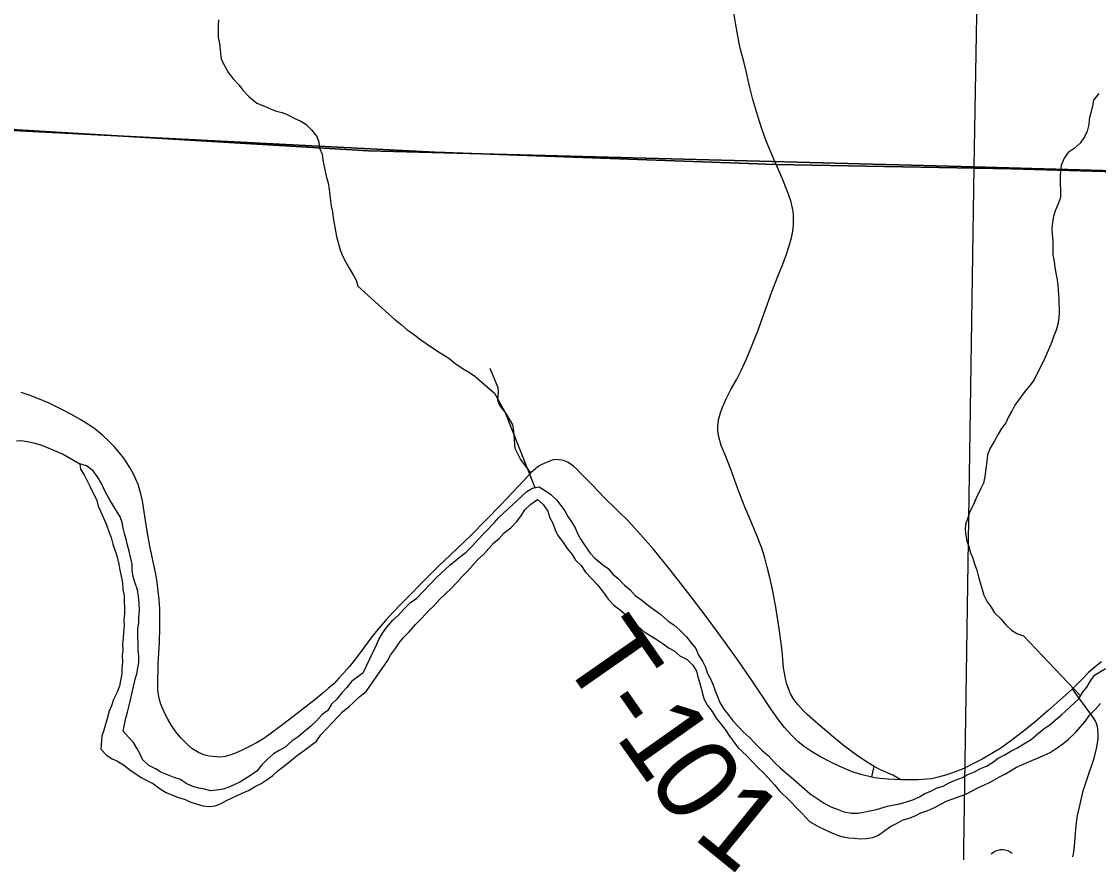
# Model space of a CAD drawing. Extents: x -3.3 to 34, y 0 to 56.8.
# Drawn here: x 2.13 to 2.868, y 32.927 to 33.496 of the extents above; entities that cross this region are included whole.
import ezdxf

# ---------------------------------------------------------------- set-up
doc = ezdxf.new("R2010")
doc.units = 0
for name, color, linetype in [('GM_X_Corporation', 7, 'Continuous'), ('GM_X_Major_River', 7, 'Continuous'), ('GM_X_Township_Road', 7, 'Continuous'), ('GM_X_Township_Road_Text', 7, 'Continuous'), ('GT_Project_Soil_Layers', 7, 'Continuous')]:
    doc.layers.add(name, color=color, linetype=linetype)

msp = doc.modelspace()

# ---------------------------------------------------------------- linework, layer by layer
at = {"layer": 'GM_X_Corporation'}
for points in [[(3.49607, 33.37476), (3.49607, 34.87705), (1.84017, 34.87705), (1.83943, 34.85654), (1.8337, 34.72257), (1.81648, 34.17132), (1.79797, 33.59224), (1.79014, 33.43939), (2.04414, 33.4254), (2.41358, 33.40641), (2.64712, 33.39799), (2.80866, 33.39507), (3.4269, 33.3772)], [(1.82548, 34.44632), (2.80077, 34.41851), (2.78283, 33.39643), (2.36801, 33.40744), (1.79067, 33.44183), (1.79698, 33.59314)], [(3.49607, 33.37604), (3.49607, 34.39505), (2.80077, 34.41851), (2.78283, 33.39643)], [(1.79067, 33.44183), (2.36801, 33.40744), (2.78283, 33.39643), (2.76783, 32.40095), (1.75455, 32.44832), (1.75705, 32.57759)], [(3.49607, 32.37106), (3.49607, 33.37604), (2.78283, 33.39643), (2.76783, 32.40095)]]:
    msp.add_lwpolyline(points, close=True, dxfattribs=at)
msp.add_lwpolyline([(3.4269, 33.3772), (2.80866, 33.39507), (2.64712, 33.39799), (2.41358, 33.40641), (2.04414, 33.4254), (1.79014, 33.43939), (1.78315, 33.26936), (1.7602, 32.71145), (1.75838, 32.6672), (1.75808, 32.65987), (1.75537, 32.59405), (1.74928, 32.44591), (1.74848, 32.4264), (1.74609, 32.36849), (1.74587, 32.36303), (1.69805, 31.56614)], dxfattribs=at)
at = {"layer": 'GM_X_Major_River'}
for points in [[(2.36432, 33.04977), (2.37352, 33.0689), (2.37499, 33.07272), (2.37759, 33.07693), (2.38057, 33.08116), (2.38469, 33.08577), (2.38844, 33.08924), (2.39218, 33.09347), (2.39705, 33.0981), (2.40081, 33.10081), (2.41467, 33.11506), (2.42367, 33.12354), (2.43118, 33.12972), (2.43494, 33.13243), (2.43869, 33.13628), (2.44243, 33.14051), (2.45404, 33.15245), (2.4574, 33.15629), (2.47653, 33.17403), (2.4803, 33.17636), (2.48484, 33.17718), (2.48867, 33.17495), (2.49289, 33.17197), (2.49673, 33.16822), (2.49982, 33.16446), (2.50253, 33.16069), (2.50448, 33.15692), (2.50719, 33.15316), (2.50952, 33.14901), (2.51148, 33.14485), (2.51343, 33.14108), (2.51962, 33.13204), (2.52309, 33.12828), (2.52847, 33.1238), (2.5323, 33.12119), (2.53539, 33.11743), (2.53923, 33.11406), (2.54346, 33.10993), (2.5473, 33.10657), (2.55077, 33.10281), (2.55537, 33.09945), (2.55998, 33.09571), (2.56841, 33.08975), (2.57341, 33.08525), (2.57724, 33.08264), (2.58185, 33.07852), (2.5857, 33.07477), (2.58918, 33.07026), (2.59227, 33.0665), (2.59423, 33.06196), (2.59694, 33.05782), (2.5989, 33.05367), (2.60008, 33.04988), (2.60242, 33.04573), (2.60399, 33.04195), (2.60557, 33.03741), (2.60714, 33.03363), (2.60871, 33.02947), (2.61143, 33.02495), (2.61452, 33.02119), (2.618, 33.01667), (2.62493, 33.00916), (2.62916, 33.00542), (2.6334, 33.00092), (2.63763, 32.99679), (2.64224, 32.99267), (2.64609, 32.98854), (2.65033, 32.98442), (2.65493, 32.98068), (2.65916, 32.97693), (2.67069, 32.96683), (2.67605, 32.9631), (2.68027, 32.9605), (2.68486, 32.95789), (2.68905, 32.95643), (2.69363, 32.95459), (2.69897, 32.95352), (2.70352, 32.95358), (2.70731, 32.95439), (2.71147, 32.95521), (2.71602, 32.95603), (2.72358, 32.95841), (2.72813, 32.95923), (2.73191, 32.96004), (2.73607, 32.96124), (2.74099, 32.96282), (2.74552, 32.96479), (2.74929, 32.96712), (2.75344, 32.96869), (2.75721, 32.97064), (2.76175, 32.97222), (2.76552, 32.97417), (2.77005, 32.97614), (2.77496, 32.9781), (2.77873, 32.98005), (2.78326, 32.98201), (2.78703, 32.98396), (2.79156, 32.98592), (2.79571, 32.98826), (2.79946, 32.99135), (2.80361, 32.99331)], [(2.3664, 33.03688), (2.38088, 33.05797), (2.38311, 33.06181), (2.38646, 33.06641), (2.38907, 33.07025), (2.39206, 33.07409), (2.3958, 33.07794), (2.40029, 33.08294), (2.40441, 33.08717), (2.40853, 33.09179), (2.41265, 33.09564), (2.41677, 33.10026), (2.42464, 33.10759), (2.42876, 33.11182), (2.43213, 33.11567), (2.43587, 33.11952), (2.44261, 33.12721), (2.44711, 33.13107), (2.45384, 33.13876), (2.4576, 33.14185), (2.46096, 33.1457), (2.46547, 33.14918), (2.46959, 33.15341), (2.47258, 33.15725), (2.47518, 33.16147), (2.4793, 33.16532), (2.48382, 33.16842), (2.48766, 33.16506), (2.49076, 33.16054), (2.49234, 33.156), (2.49429, 33.15222), (2.49587, 33.14768), (2.49782, 33.14391), (2.50091, 33.13977), (2.50401, 33.13487), (2.50749, 33.13074), (2.50982, 33.12697), (2.51366, 33.12322), (2.51676, 33.1187), (2.52485, 33.11007), (2.5291, 33.1048), (2.5322, 33.10028), (2.53605, 33.09615), (2.54065, 33.09279), (2.54565, 33.0883), (2.54949, 33.08493), (2.55296, 33.08118), (2.5568, 33.07781), (2.56446, 33.07335), (2.56982, 33.06962), (2.57366, 33.06701), (2.57748, 33.06478), (2.58132, 33.06141), (2.5863, 33.05882), (2.59014, 33.05507), (2.59286, 33.05092), (2.59367, 33.04713), (2.59486, 33.04335), (2.59605, 33.03918), (2.59686, 33.03539), (2.59805, 33.03161), (2.60039, 33.02746), (2.60348, 33.02332), (2.6062, 33.0188), (2.60929, 33.01504), (2.61238, 33.0109), (2.61548, 33.00638), (2.61819, 33.00261), (2.62128, 32.99847), (2.62705, 32.99323), (2.6309, 32.9891), (2.63437, 32.98535), (2.63937, 32.98047), (2.6463, 32.97296), (2.64939, 32.9692), (2.65747, 32.96133), (2.66133, 32.9572), (2.66517, 32.95345), (2.67018, 32.94782), (2.67707, 32.94411), (2.68548, 32.94004), (2.6893, 32.93857), (2.69311, 32.93748), (2.69691, 32.93677), (2.70109, 32.93645), (2.7049, 32.93612), (2.70907, 32.93617), (2.71362, 32.937), (2.71739, 32.93857), (2.72191, 32.94167), (2.72567, 32.94438), (2.72944, 32.94633), (2.73434, 32.94905), (2.7385, 32.95025), (2.74266, 32.95182), (2.74643, 32.95378), (2.75134, 32.95536), (2.75549, 32.95732), (2.76454, 32.962), (2.76908, 32.96358), (2.77285, 32.96515)], [(2.80361, 32.99331), (2.80813, 32.99603), (2.81266, 32.99837), (2.81718, 33.00109), (2.82207, 33.00419), (2.82583, 33.00728), (2.83109, 33.01154), (2.83485, 33.01425), (2.8386, 33.01734), (2.84273, 33.02081), (2.85473, 33.032), (2.85734, 33.03621), (2.86032, 33.04005), (2.86255, 33.04388), (2.86553, 33.0481), (2.87306, 33.05276)], [(2.77285, 32.96515), (2.77739, 32.96673), (2.78644, 32.97141), (2.79022, 32.97299), (2.79399, 32.97494), (2.8004, 32.97844), (2.80417, 32.98039), (2.80793, 32.98272), (2.81208, 32.98506), (2.81736, 32.98741), (2.82265, 32.98976), (2.82642, 32.99133), (2.83095, 32.99329), (2.8351, 32.99525), (2.84, 32.99835), (2.84376, 33.00107), (2.84751, 33.00415), (2.85239, 33.00878), (2.85912, 33.01647), (2.8621, 33.02069), (2.86622, 33.02493), (2.86959, 33.02877)]]:
    msp.add_lwpolyline(points, dxfattribs=at)
at = {"layer": 'GM_X_Township_Road'}
for points in [[(2.64306, 33.40812), (2.64, 33.41532), (2.63746, 33.42258), (2.63475, 33.43116), (2.63146, 33.44258), (2.62899, 33.45179), (2.62694, 33.461), (2.62513, 33.46865), (2.62274, 33.47769), (2.62167, 33.48229), (2.61954, 33.49511), (2.61781, 33.50481)], [(2.73274, 32.9765), (2.72726, 32.97959), (2.71883, 32.98333), (2.71446, 32.98551), (2.7085, 32.9892), (2.7021, 32.99366), (2.69449, 32.99921), (2.68672, 33.00568), (2.67581, 33.01483), (2.66855, 33.02125), (2.66564, 33.02408), (2.66222, 33.02796), (2.65944, 33.03148), (2.65722, 33.03536), (2.65593, 33.03841), (2.65454, 33.04267), (2.65357, 33.04697), (2.65302, 33.04958), (2.65249, 33.05325), (2.65139, 33.06477), (2.64964, 33.07864), (2.64706, 33.09469), (2.64482, 33.10697), (2.64284, 33.11599), (2.64128, 33.12212), (2.63962, 33.1285), (2.63747, 33.1352), (2.63506, 33.14165), (2.63216, 33.14883), (2.62605, 33.16289), (2.62125, 33.1751), (2.61662, 33.1886), (2.61283, 33.1979), (2.60969, 33.20558), (2.60806, 33.21151), (2.60744, 33.2153), (2.6073, 33.21885), (2.60792, 33.22314), (2.60921, 33.22787), (2.61052, 33.23172), (2.6132, 33.23761), (2.6164, 33.2439), (2.62036, 33.25108), (2.62327, 33.25701), (2.62698, 33.26489), (2.63077, 33.27377), (2.63466, 33.28339), (2.639, 33.2955), (2.64363, 33.30891), (2.64834, 33.32084), (2.65186, 33.32981), (2.65417, 33.33591), (2.6563, 33.34239), (2.65778, 33.34775), (2.6587, 33.35237), (2.65925, 33.35663), (2.65935, 33.36097), (2.65925, 33.36449), (2.65861, 33.36819), (2.65732, 33.37318), (2.65546, 33.37892), (2.65139, 33.38872), (2.6465, 33.4), (2.64344, 33.40722), (2.64306, 33.40812)], [(2.47911, 33.18675), (2.4722, 33.19606), (2.46838, 33.20337), (2.46764, 33.21549), (2.46693, 33.21961), (2.46242, 33.22749), (2.4577, 33.23329), (2.45654, 33.23661), (2.45709, 33.24222), (2.45684, 33.24508), (2.4514, 33.25821)], [(2.73274, 32.9765), (2.72404, 32.97682), (2.71874, 32.97737), (2.71498, 32.97786), (2.71299, 32.97825), (2.70542, 32.98005), (2.6989, 32.98226), (2.69098, 32.98552), (2.68482, 32.98852), (2.67777, 32.99222), (2.67157, 32.99592), (2.66675, 32.99913), (2.66241, 33.00257), (2.65761, 33.00738), (2.65303, 33.01241), (2.64846, 33.01825), (2.64366, 33.0251), (2.63176, 33.04283), (2.6217, 33.05747), (2.61198, 33.07131), (2.59929, 33.08846), (2.58682, 33.10481), (2.5747, 33.12026), (2.56315, 33.13466), (2.55422, 33.14484), (2.54611, 33.15376), (2.53822, 33.16154), (2.52941, 33.17), (2.52129, 33.17848), (2.51306, 33.1868), (2.51065, 33.1892), (2.50851, 33.19126), (2.50628, 33.19289), (2.50431, 33.19417), (2.50225, 33.19503), (2.50036, 33.19555), (2.49813, 33.1958), (2.49616, 33.19589), (2.49393, 33.19546), (2.49007, 33.19398), (2.48687, 33.19257), (2.48492, 33.19155), (2.48262, 33.18983), (2.47911, 33.18675), (2.47443, 33.18165), (2.45868, 33.16476), (2.43835, 33.144), (2.42818, 33.13453), (2.41605, 33.1229), (2.40413, 33.11107), (2.39615, 33.10275), (2.39044, 33.09713), (2.38491, 33.09142), (2.37961, 33.08563), (2.37441, 33.07957), (2.37034, 33.07447), (2.36529, 33.06765), (2.35991, 33.06047), (2.35487, 33.05415), (2.35058, 33.04934), (2.34769, 33.04605), (2.34434, 33.04253), (2.3406, 33.03921), (2.33667, 33.0358), (2.33139, 33.03147), (2.32206, 33.02424), (2.30922, 33.01429), (2.2994, 33.00711), (2.29545, 33.00436), (2.29112, 33.00188), (2.28679, 32.99947), (2.28144, 32.99689), (2.27676, 32.99476), (2.27292, 32.99328), (2.2698, 32.99255), (2.26627, 32.99209), (2.25883, 32.99261), (2.25506, 32.99356), (2.25146, 32.99527), (2.24699, 32.99801), (2.24313, 33.00128), (2.23905, 33.00535), (2.23596, 33.00929), (2.23299, 33.01363), (2.23039, 33.01797), (2.22812, 33.02229), (2.22649, 33.02606), (2.22516, 33.02968), (2.22426, 33.03352), (2.22367, 33.03772), (2.22358, 33.0415), (2.22392, 33.05583), (2.22469, 33.07084), (2.22495, 33.08079), (2.22503, 33.08739), (2.22487, 33.09357), (2.22444, 33.1), (2.2238, 33.10581), (2.22313, 33.11195), (2.22224, 33.11727), (2.22067, 33.12497), (2.21817, 33.13645), (2.2162, 33.14674), (2.21461, 33.1572), (2.21304, 33.1676), (2.21195, 33.17243), (2.21001, 33.17881), (2.20862, 33.18246), (2.20628, 33.18725), (2.20442, 33.19051), (2.2024, 33.1937), (2.20023, 33.19679), (2.1974, 33.2004), (2.19356, 33.20479), (2.19016, 33.20835), (2.18559, 33.21256), (2.18034, 33.21687), (2.17639, 33.21968), (2.17075, 33.22317), (2.16387, 33.22692), (2.15772, 33.23023), (2.14922, 33.2345), (2.14021, 33.23826), (2.13477, 33.24025), (2.12985, 33.24193)], [(2.87032, 33.05724), (2.86609, 33.05392), (2.86143, 33.04989), (2.8574, 33.04558), (2.85042, 33.03871)], [(2.85042, 33.03871), (2.8436, 33.03253), (2.83386, 33.02407), (2.82454, 33.01598), (2.81582, 33.00892), (2.80818, 33.00309), (2.80127, 32.99825), (2.79525, 32.99442), (2.78852, 32.99065), (2.78204, 32.98736), (2.77596, 32.98427), (2.77001, 32.98188), (2.76425, 32.97988), (2.75833, 32.97822), (2.75382, 32.9772), (2.75078, 32.97685), (2.74475, 32.97639), (2.73274, 32.9765)], [(2.85074, 32.92373), (2.85137, 32.92698), (2.85211, 32.93341), (2.8526, 32.94009), (2.85312, 32.94709), (2.8539, 32.95196), (2.85497, 32.95676), (2.85785, 32.96882), (2.86048, 32.9771), (2.86528, 32.99126), (2.86687, 32.99785), (2.86757, 33.00164), (2.86797, 33.00473), (2.86807, 33.00812), (2.86787, 33.01081), (2.86754, 33.01293), (2.86701, 33.01495), (2.86597, 33.0171), (2.86437, 33.01959), (2.85979, 33.02568), (2.8541, 33.03356), (2.85042, 33.03871)], [(2.71299, 32.97825), (2.7137, 32.98176), (2.71446, 32.98551)], [(2.79477, 32.92572), (2.79625, 32.92692), (2.79794, 32.92782), (2.79946, 32.92828), (2.80111, 32.92865), (2.80262, 32.92874), (2.80414, 32.92861), (2.80608, 32.92809), (2.80772, 32.92722), (2.80912, 32.92623)]]:
    msp.add_lwpolyline(points, dxfattribs=at)
at = {"layer": 'GT_Project_Soil_Layers'}
for points in [[(2.26518, 33.4972), (2.26486, 33.49301), (2.26497, 33.48503), (2.26579, 33.48087), (2.26622, 33.47669), (2.26707, 33.47025), (2.26941, 33.46534), (2.27213, 33.46082), (2.27522, 33.45668), (2.27907, 33.45256), (2.28216, 33.4488), (2.28601, 33.44467), (2.29138, 33.44018), (2.29672, 33.43798), (2.30091, 33.43614), (2.30473, 33.43467), (2.30891, 33.43359), (2.31272, 33.43212), (2.31693, 33.4299), (2.32151, 33.42768), (2.32533, 33.42545), (2.32879, 33.4217), (2.33265, 33.41719), (2.33384, 33.41341), (2.33466, 33.40886), (2.33623, 33.40508), (2.33667, 33.40091), (2.33829, 33.39333), (2.3391, 33.38917), (2.34029, 33.38538), (2.34112, 33.38083), (2.34155, 33.37704), (2.34198, 33.37325), (2.34241, 33.36945), (2.34322, 33.36567), (2.34366, 33.36149), (2.34447, 33.3577), (2.34611, 33.34861), (2.34852, 33.33952), (2.35048, 33.33499), (2.35242, 33.33121), (2.35476, 33.32706), (2.35748, 33.32254), (2.35942, 33.31877), (2.36062, 33.3146)], [(2.86856, 33.44677), (2.86482, 33.44216), (2.86411, 33.43835), (2.86304, 33.43339), (2.86196, 33.4292), (2.86162, 33.4254), (2.86055, 33.42082), (2.8587, 33.417), (2.85572, 33.41278), (2.85159, 33.40893), (2.84745, 33.40621), (2.84484, 33.40238), (2.84263, 33.39741), (2.8423, 33.3936), (2.84197, 33.3898), (2.84217, 33.37536), (2.8407, 33.37117), (2.83849, 33.3662), (2.8374, 33.36238), (2.83669, 33.35857), (2.83637, 33.35401), (2.83643, 33.35021), (2.83686, 33.34604), (2.83699, 33.33616), (2.83781, 33.33161), (2.83825, 33.32744), (2.83906, 33.32365), (2.83988, 33.3191), (2.84031, 33.31531), (2.84119, 33.30582), (2.84132, 33.2967), (2.84099, 33.29289), (2.84029, 33.28871), (2.8392, 33.28451), (2.83773, 33.28069)], [(2.36062, 33.3146), (2.38187, 33.29551), (2.38572, 33.29214), (2.39033, 33.28841), (2.39417, 33.28504), (2.39953, 33.28131), (2.40376, 33.27795), (2.40758, 33.27534), (2.4118, 33.27235), (2.41716, 33.269), (2.42291, 33.26528), (2.42713, 33.26192), (2.43211, 33.25856), (2.43709, 33.25559), (2.44092, 33.25298), (2.45437, 33.24138), (2.46149, 33.22851), (2.48195, 33.17666)], [(2.83773, 33.28069), (2.83627, 33.27649), (2.83443, 33.27229), (2.83222, 33.26694), (2.83001, 33.26235), (2.82778, 33.25814), (2.82409, 33.25049), (2.8211, 33.24665), (2.81774, 33.24242), (2.81103, 33.23321), (2.80881, 33.22901), (2.80658, 33.22517), (2.80474, 33.22097), (2.80175, 33.21713), (2.79952, 33.2133), (2.79693, 33.20871), (2.79396, 33.20373), (2.79212, 33.19914), (2.7918, 33.19458), (2.79111, 33.18963), (2.79042, 33.1843), (2.78934, 33.17972), (2.7875, 33.17552), (2.78454, 33.1694), (2.7827, 33.16519), (2.78011, 33.16022), (2.77865, 33.15602), (2.77719, 33.15144), (2.77686, 33.14763), (2.77729, 33.14384), (2.7781, 33.14005), (2.77929, 33.13626), (2.78049, 33.1321), (2.78206, 33.12832), (2.78325, 33.12453), (2.78483, 33.12), (2.78603, 33.11545), (2.78961, 33.10296), (2.79195, 33.09843), (2.79466, 33.09466), (2.79699, 33.09089), (2.80122, 33.08677), (2.80469, 33.08264), (2.80854, 33.07889), (2.81237, 33.07666), (2.81694, 33.0752), (2.85601, 33.03406)], [(2.12662, 33.2088), (2.13041, 33.20885), (2.13633, 33.2079), (2.13954, 33.20707), (2.14449, 33.20562), (2.1588, 33.19963), (2.17007, 33.19305)], [(2.36432, 33.04977), (2.36057, 33.04706), (2.35644, 33.04396), (2.35309, 33.03973), (2.34935, 33.03588), (2.34637, 33.03166), (2.34263, 33.02819), (2.34004, 33.02397), (2.33628, 33.02126), (2.33218, 33.01664), (2.32843, 33.01317), (2.32431, 33.0097), (2.31981, 33.00583), (2.31568, 33.00312), (2.31081, 32.99887), (2.30667, 32.99653), (2.30291, 32.9942), (2.29842, 32.99034), (2.29468, 32.98648), (2.2917, 32.98264), (2.28719, 32.97954), (2.27967, 32.97488), (2.27591, 32.97292), (2.27214, 32.97135), (2.26837, 32.97016), (2.26383, 32.96934), (2.25966, 32.9689), (2.25548, 32.96999), (2.25167, 32.97069), (2.24749, 32.97178), (2.24291, 32.97399), (2.23908, 32.9766), (2.23489, 32.97807), (2.22573, 32.98174), (2.22191, 32.98397), (2.21733, 32.98619), (2.2131, 32.99031), (2.21153, 32.99409), (2.2092, 32.99824), (2.20687, 33.00201), (2.20341, 33.00576), (2.19993, 33.00989), (2.20063, 33.01446), (2.20171, 33.01866), (2.20279, 33.02285), (2.20386, 33.02743), (2.20494, 33.03125), (2.20601, 33.0362), (2.20816, 33.04535), (2.20924, 33.04917), (2.20995, 33.05298), (2.21065, 33.05717), (2.21059, 33.06135), (2.21016, 33.06514), (2.20995, 33.07958), (2.21065, 33.08415), (2.21059, 33.08795), (2.21091, 33.09252), (2.21084, 33.09746), (2.2104, 33.10201), (2.20958, 33.10656), (2.208, 33.1111), (2.20679, 33.11564), (2.20597, 33.12019), (2.20591, 33.12437), (2.2051, 33.12816), (2.2039, 33.13309), (2.2027, 33.13725), (2.20188, 33.14142), (2.20069, 33.14521), (2.19988, 33.149), (2.19907, 33.15278), (2.19788, 33.15657), (2.1909, 33.16787), (2.18856, 33.17202), (2.18662, 33.1758), (2.18505, 33.17957), (2.18233, 33.1841), (2.17924, 33.18824), (2.17464, 33.19159), (2.17007, 33.19305), (2.1705, 33.18926), (2.17321, 33.18549), (2.17516, 33.18134), (2.1775, 33.17681), (2.1818, 33.16775), (2.18261, 33.16396), (2.18456, 33.16019), (2.18848, 33.15112), (2.19006, 33.14658), (2.19163, 33.14242), (2.19283, 33.13788), (2.19402, 33.13409), (2.1956, 33.12993), (2.19681, 33.12425), (2.19763, 33.12008), (2.19845, 33.11591), (2.19927, 33.11136), (2.19971, 33.10681), (2.20053, 33.10264), (2.2007, 33.09048)], [(2.2007, 33.09048), (2.20039, 33.08591), (2.20044, 33.08211), (2.20012, 33.07755), (2.1998, 33.07374), (2.19948, 33.06918), (2.19954, 33.06538), (2.19921, 33.06157), (2.19927, 33.05701), (2.19895, 33.05283), (2.19901, 33.04903), (2.19793, 33.04445), (2.19723, 33.04064), (2.1954, 33.03606), (2.19318, 33.03146), (2.19173, 33.02726), (2.19026, 33.02344), (2.18919, 33.01925), (2.18666, 33.01047), (2.1852, 33.00627), (2.18456, 32.99752), (2.18841, 32.99339), (2.19224, 32.99078), (2.19605, 32.98932), (2.20064, 32.98634), (2.20448, 32.98335), (2.21213, 32.97813), (2.21596, 32.97591), (2.22054, 32.97369), (2.22514, 32.97033), (2.22934, 32.96773), (2.23354, 32.96589), (2.23773, 32.96442), (2.2423, 32.96296), (2.24612, 32.96112), (2.24993, 32.96003), (2.2545, 32.95857), (2.25905, 32.95825), (2.26284, 32.95868), (2.26699, 32.96026), (2.27075, 32.96221), (2.2813, 32.9673), (2.28582, 32.96926), (2.29033, 32.97198), (2.29448, 32.97394), (2.29861, 32.97666), (2.30236, 32.97937), (2.30611, 32.98284), (2.31061, 32.98632), (2.31548, 32.99019), (2.31923, 32.99328), (2.32411, 32.99677), (2.33237, 33.00296), (2.33534, 33.00718), (2.33907, 33.01142), (2.34692, 33.01951), (2.35028, 33.02335), (2.35441, 33.02645), (2.36227, 33.03378), (2.3664, 33.03688)]]:
    msp.add_lwpolyline(points, dxfattribs=at)

# ---------------------------------------------------------------- texts
at = {"layer": 'GM_X_Township_Road_Text'}
for s, rotation, p in [('T', 304.89302, (2.49859, 33.06067)), ('-', 304.96332, (2.52295, 33.02575)), ('1', 305.29394, (2.53652, 33.00633)), ('0', 306.60074, (2.55757, 32.97662)), ('1', 320.90343, (2.58911, 32.93738))]:
    msp.add_text(s, height=0.05682, rotation=rotation, dxfattribs=at).set_placement(p)

doc.saveas('drawing.dxf')
